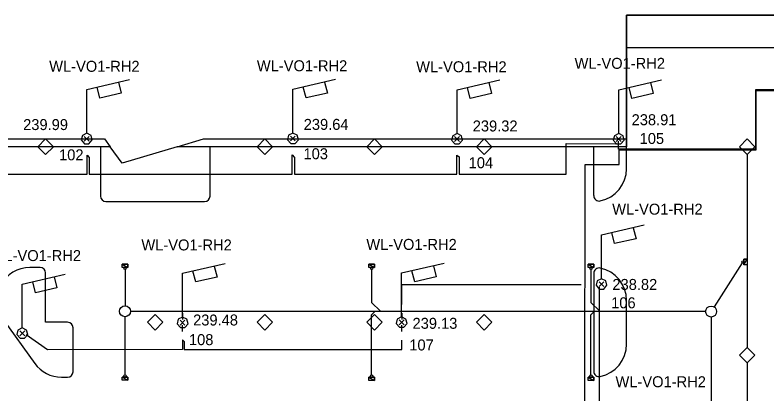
# Model space of a CAD drawing. Extents: x -264222 to -263592, y -1242345 to -1242048.
# Drawn here: x -264187.4 to -264118.8, y -1242214 to -1242179.5 of the extents above; entities that cross this region are included whole.
import ezdxf

# ---------------------------------------------------------------- set-up
doc = ezdxf.new("R2010")
doc.units = 0
for name, color, linetype in [('BOD_CISLO', 7, 'Continuous'), ('BOD_SYMBOL', 7, 'Continuous'), ('BOD_VYSKA', 7, 'Continuous'), ('KFA_2D_SITUACIA_DSP', 7, 'Continuous'), ('KFA_SO_62-1_VO_LAMPY_MERANE', 7, 'Continuous'), ('KFA_SO_62-1_VO_POPIS_LAMP_PROJEKT', 7, 'Continuous'), ('KFA_SO_62-1_VO_TRASA_KABLOV_PROJEKT', 7, 'Continuous')]:
    doc.layers.add(name, color=color, linetype=linetype)

msp = doc.modelspace()

# ---------------------------------------------------------------- linework, layer by layer
at = {"layer": 'BOD_SYMBOL'}
for p, q in [((-264181.038, -1242190.978), (-264180.596, -1242190.536)), ((-264180.596, -1242190.978), (-264181.038, -1242190.536)), ((-264162.233, -1242190.96), (-264161.791, -1242190.518)), ((-264161.791, -1242190.96), (-264162.233, -1242190.518)), ((-264147.253, -1242191.004), (-264146.811, -1242190.562)), ((-264146.811, -1242191.004), (-264147.253, -1242190.562)), ((-264132.505, -1242191.004), (-264132.063, -1242190.562)), ((-264132.063, -1242191.004), (-264132.505, -1242190.562)), ((-264134.077, -1242204.234), (-264133.635, -1242203.792)), ((-264133.635, -1242204.234), (-264134.077, -1242203.792)), ((-264172.299, -1242207.73), (-264171.857, -1242207.288)), ((-264171.857, -1242207.73), (-264172.299, -1242207.288)), ((-264152.316, -1242207.709), (-264151.874, -1242207.267)), ((-264151.874, -1242207.709), (-264152.316, -1242207.267)), ((-264186.919, -1242208.714), (-264186.477, -1242208.272)), ((-264186.477, -1242208.714), (-264186.919, -1242208.272))]:
    msp.add_line(p, q, dxfattribs=at)
at = {"layer": 'KFA_2D_SITUACIA_DSP'}
for p, q in [((-264131.568, -1242193.482), (-264131.568, -1242179.482)), ((-264077.23, -1242179.482), (-264131.568, -1242179.482)), ((-264131.568, -1242179.482), (-264131.568, -1242191.482)), ((-264131.568, -1242179.482), (-263959.468, -1242179.482)), ((-263959.468, -1242179.482), (-264131.568, -1242179.482)), ((-264045.204, -1242182.482), (-264131.568, -1242182.482)), ((-264205.202, -1242190.775), (-264179.193, -1242190.775)), ((-264179.193, -1242190.775), (-264178.679, -1242191.482)), ((-264172.558, -1242191.482), (-264170.162, -1242190.775)), ((-264170.162, -1242190.775), (-264131.568, -1242190.775)), ((-264178.679, -1242191.482), (-264204.694, -1242191.482)), ((-264179.568, -1242191.482), (-264204.078, -1242191.482)), ((-264179.568, -1242191.482), (-264179.568, -1242195.982)), ((-264177.6, -1242192.97), (-264178.679, -1242191.482)), ((-264172.558, -1242191.482), (-264177.6, -1242192.97)), ((-264131.568, -1242191.482), (-264172.558, -1242191.482)), ((-264134.568, -1242191.482), (-264169.568, -1242191.482)), ((-264169.568, -1242195.982), (-264169.568, -1242191.482)), ((-264134.568, -1242195.932), (-264134.568, -1242191.482)), ((-264120.568, -1242192.189), (-264120.568, -1242209.775)), ((-264179.068, -1242196.482), (-264170.068, -1242196.482)), ((-264121.012, -1242202.066), (-264123.585, -1242206.079)), ((-264120.858, -1242202.232), (-264120.858, -1242201.732)), ((-264120.858, -1242201.732), (-264120.568, -1242201.732)), ((-264120.858, -1242202.232), (-264120.568, -1242201.732)), ((-264120.858, -1242202.232), (-264120.568, -1242201.732)), ((-264120.568, -1242201.732), (-264120.858, -1242201.732)), ((-264120.858, -1242201.732), (-264120.858, -1242202.232)), ((-264120.568, -1242201.732), (-264120.568, -1242202.232)), ((-264185.068, -1242202.482), (-264186.002, -1242202.482)), ((-264177.574, -1242202.186), (-264177.074, -1242202.186)), ((-264177.574, -1242202.476), (-264177.574, -1242202.186)), ((-264177.574, -1242202.186), (-264177.074, -1242202.476)), ((-264177.574, -1242202.186), (-264177.074, -1242202.476)), ((-264177.074, -1242202.186), (-264177.574, -1242202.186)), ((-264177.074, -1242202.476), (-264177.574, -1242202.476)), ((-264177.324, -1242202.676), (-264177.324, -1242205.976)), ((-264177.074, -1242202.186), (-264177.074, -1242202.476)), ((-264177.074, -1242202.476), (-264177.074, -1242202.186)), ((-264155.074, -1242202.192), (-264154.574, -1242202.192)), ((-264155.074, -1242202.482), (-264155.074, -1242202.192)), ((-264155.074, -1242202.192), (-264154.574, -1242202.482)), ((-264155.074, -1242202.192), (-264154.574, -1242202.482)), ((-264154.574, -1242202.192), (-264155.074, -1242202.192)), ((-264154.574, -1242202.482), (-264155.074, -1242202.482)), ((-264154.824, -1242202.682), (-264154.824, -1242205.68)), ((-264154.574, -1242202.192), (-264154.574, -1242202.482)), ((-264154.574, -1242202.482), (-264154.574, -1242202.192)), ((-264135.068, -1242202.192), (-264134.568, -1242202.192)), ((-264135.068, -1242202.482), (-264135.068, -1242202.192)), ((-264135.068, -1242202.192), (-264134.568, -1242202.482)), ((-264135.068, -1242202.192), (-264134.568, -1242202.482)), ((-264134.568, -1242202.192), (-264135.068, -1242202.192)), ((-264134.568, -1242202.482), (-264135.068, -1242202.482)), ((-264134.818, -1242202.682), (-264134.818, -1242205.68)), ((-264134.568, -1242202.192), (-264134.568, -1242202.482)), ((-264134.568, -1242202.482), (-264134.568, -1242202.192)), ((-264120.568, -1242202.232), (-264120.858, -1242202.232)), ((-264134.568, -1242203.033), (-264134.568, -1242211.932)), ((-264131.568, -1242209.482), (-264131.568, -1242205.482)), ((-264154.824, -1242205.68), (-264154.029, -1242206.476)), ((-264134.818, -1242205.68), (-264134.023, -1242206.476)), ((-264176.824, -1242206.476), (-264124.354, -1242206.476)), ((-264154.824, -1242206.801), (-264154.499, -1242206.476)), ((-264154.824, -1242212.282), (-264154.824, -1242206.801)), ((-264134.818, -1242206.801), (-264134.493, -1242206.476)), ((-264134.818, -1242212.282), (-264134.818, -1242206.801)), ((-264188.438, -1242207.234), (-264185.561, -1242211.234)), ((-264177.324, -1242212.276), (-264177.324, -1242206.976)), ((-264123.854, -1242207), (-264123.854, -1242236.976)), ((-264182.068, -1242211.982), (-264182.068, -1242207.982)), ((-264120.568, -1242211.189), (-264120.568, -1242219.774)), ((-264183.125, -1242212.482), (-264182.568, -1242212.482)), ((-264177.574, -1242212.476), (-264177.074, -1242212.476)), ((-264177.574, -1242212.766), (-264177.574, -1242212.476)), ((-264177.574, -1242212.476), (-264177.074, -1242212.766)), ((-264177.574, -1242212.476), (-264177.074, -1242212.766)), ((-264177.074, -1242212.476), (-264177.574, -1242212.476)), ((-264177.074, -1242212.766), (-264177.574, -1242212.766)), ((-264177.074, -1242212.476), (-264177.074, -1242212.766)), ((-264177.074, -1242212.766), (-264177.074, -1242212.476)), ((-264155.074, -1242212.482), (-264154.574, -1242212.482)), ((-264155.074, -1242212.772), (-264155.074, -1242212.482)), ((-264155.074, -1242212.482), (-264154.574, -1242212.772)), ((-264155.074, -1242212.482), (-264154.574, -1242212.772)), ((-264154.574, -1242212.482), (-264155.074, -1242212.482)), ((-264154.574, -1242212.772), (-264155.074, -1242212.772)), ((-264154.574, -1242212.482), (-264154.574, -1242212.772)), ((-264154.574, -1242212.772), (-264154.574, -1242212.482)), ((-264135.068, -1242212.482), (-264134.568, -1242212.482)), ((-264135.068, -1242212.772), (-264135.068, -1242212.482)), ((-264135.068, -1242212.482), (-264134.568, -1242212.772)), ((-264135.068, -1242212.482), (-264134.568, -1242212.772)), ((-264134.568, -1242212.482), (-264135.068, -1242212.482)), ((-264134.568, -1242212.772), (-264135.068, -1242212.772)), ((-264134.568, -1242212.482), (-264134.568, -1242212.772)), ((-264134.568, -1242212.772), (-264134.568, -1242212.482))]:
    msp.add_line(p, q, dxfattribs=at)
for points in [[(-264184.568, -1242190.775), (-264183.861, -1242191.482), (-264184.568, -1242192.189), (-264185.275, -1242191.482)], [(-264164.568, -1242190.775), (-264163.861, -1242191.482), (-264164.568, -1242192.189), (-264165.275, -1242191.482)], [(-264154.568, -1242190.775), (-264153.861, -1242191.482), (-264154.568, -1242192.189), (-264155.275, -1242191.482)], [(-264144.568, -1242190.775), (-264143.861, -1242191.482), (-264144.568, -1242192.189), (-264145.275, -1242191.482)], [(-264120.568, -1242190.775), (-264119.861, -1242191.482), (-264120.568, -1242192.189), (-264121.275, -1242191.482)], [(-264173.861, -1242207.482), (-264174.568, -1242206.775), (-264175.275, -1242207.482), (-264174.568, -1242208.189)], [(-264163.861, -1242207.482), (-264164.568, -1242206.775), (-264165.275, -1242207.482), (-264164.568, -1242208.189)], [(-264153.861, -1242207.482), (-264154.568, -1242206.775), (-264155.275, -1242207.482), (-264154.568, -1242208.189)], [(-264143.861, -1242207.482), (-264144.568, -1242206.775), (-264145.275, -1242207.482), (-264144.568, -1242208.189)], [(-264120.568, -1242209.775), (-264119.861, -1242210.482), (-264120.568, -1242211.189), (-264121.275, -1242210.482)]]:
    msp.add_lwpolyline(points, close=True, dxfattribs=at)
for points in [[(-264183.861, -1242191.482), (-264183.861, -1242191.482), (-264184.568, -1242192.189), (-264185.275, -1242191.482)], [(-264163.861, -1242191.482), (-264163.861, -1242191.482), (-264164.568, -1242192.189), (-264165.275, -1242191.482)], [(-264153.861, -1242191.482), (-264153.861, -1242191.482), (-264154.568, -1242192.189), (-264155.275, -1242191.482)], [(-264143.861, -1242191.482), (-264143.861, -1242191.482), (-264144.568, -1242192.189), (-264145.275, -1242191.482)], [(-264182.568, -1242207.482), (-264184.568, -1242207.482), (-264184.568, -1242202.982)]]:
    msp.add_lwpolyline(points, dxfattribs=at)
for centre, radius in [((-264120.958, -1242201.982), 0.1), ((-264177.324, -1242202.576), 0.1), ((-264154.824, -1242202.582), 0.1), ((-264134.818, -1242202.582), 0.1), ((-264177.324, -1242206.476), 0.5), ((-264123.854, -1242206.5), 0.5), ((-264177.324, -1242212.376), 0.1), ((-264154.824, -1242212.382), 0.1), ((-264134.818, -1242212.382), 0.1)]:
    msp.add_circle(centre, radius, dxfattribs=at)
for centre, radius, start, end in [((-264134.568, -1242193.482), 3, 281.53696, 0), ((-264179.068, -1242195.982), 0.5, 180, 270), ((-264170.068, -1242195.982), 0.5, 270, 0), ((-264134.068, -1242195.932), 0.5, 180, 281.53696), ((-264186.002, -1242205.482), 3, 90, 215.72401), ((-264185.068, -1242202.982), 0.5, 0, 90), ((-264134.068, -1242203.033), 0.5, 78.46304, 180), ((-264134.568, -1242205.482), 3, 0, 78.46304), ((-264182.568, -1242207.982), 0.5, 0, 90), ((-264134.568, -1242209.482), 3, 281.53696, 0), ((-264183.125, -1242209.482), 3, 215.72401, 270), ((-264182.568, -1242211.982), 0.5, 270, 0), ((-264134.068, -1242211.932), 0.5, 180, 281.53696)]:
    msp.add_arc(centre, radius, start, end, dxfattribs=at)
at = {"layer": 'KFA_SO_62-1_VO_LAMPY_MERANE'}
for p, q in [((-264180.867, -1242190.757), (-264180.767, -1242190.757)), ((-264180.817, -1242190.757), (-264180.817, -1242190.757)), ((-264162.062, -1242190.739), (-264161.962, -1242190.739)), ((-264162.012, -1242190.739), (-264162.012, -1242190.739)), ((-264147.082, -1242190.783), (-264146.982, -1242190.783)), ((-264147.032, -1242190.783), (-264147.032, -1242190.783)), ((-264132.334, -1242190.783), (-264132.234, -1242190.783)), ((-264132.284, -1242190.783), (-264132.284, -1242190.783)), ((-264133.906, -1242204.013), (-264133.806, -1242204.013)), ((-264133.856, -1242204.013), (-264133.856, -1242204.013)), ((-264172.128, -1242207.509), (-264172.028, -1242207.509)), ((-264172.078, -1242207.509), (-264172.078, -1242207.509)), ((-264152.145, -1242207.488), (-264152.045, -1242207.488)), ((-264152.095, -1242207.488), (-264152.095, -1242207.488)), ((-264186.748, -1242208.493), (-264186.648, -1242208.493)), ((-264186.698, -1242208.493), (-264186.698, -1242208.493))]:
    msp.add_line(p, q, dxfattribs=at)
for points in [[(-264180.817, -1242190.257), (-264181.217, -1242190.457), (-264181.317, -1242190.857), (-264181.017, -1242191.207), (-264180.617, -1242191.207), (-264180.317, -1242190.857), (-264180.417, -1242190.457), (-264180.817, -1242190.257), (-264180.817, -1242186.257), (-264176.917, -1242185.357)], [(-264177.917, -1242185.607), (-264177.667, -1242186.607), (-264179.617, -1242187.057), (-264179.867, -1242186.057)], [(-264162.012, -1242190.239), (-264162.412, -1242190.439), (-264162.512, -1242190.839), (-264162.212, -1242191.189), (-264161.812, -1242191.189), (-264161.512, -1242190.839), (-264161.612, -1242190.439), (-264162.012, -1242190.239), (-264162.012, -1242186.239), (-264158.112, -1242185.339)], [(-264159.112, -1242185.589), (-264158.862, -1242186.589), (-264160.812, -1242187.039), (-264161.062, -1242186.039)], [(-264147.032, -1242190.283), (-264147.432, -1242190.483), (-264147.532, -1242190.883), (-264147.232, -1242191.233), (-264146.832, -1242191.233), (-264146.532, -1242190.883), (-264146.632, -1242190.483), (-264147.032, -1242190.283), (-264147.032, -1242186.283), (-264143.132, -1242185.383)], [(-264132.284, -1242190.283), (-264132.684, -1242190.483), (-264132.784, -1242190.883), (-264132.484, -1242191.233), (-264132.084, -1242191.233), (-264131.784, -1242190.883), (-264131.884, -1242190.483), (-264132.284, -1242190.283), (-264132.284, -1242186.283), (-264128.384, -1242185.383)], [(-264144.132, -1242185.633), (-264143.882, -1242186.633), (-264145.832, -1242187.083), (-264146.082, -1242186.083)], [(-264129.384, -1242185.633), (-264129.134, -1242186.633), (-264131.084, -1242187.083), (-264131.334, -1242186.083)], [(-264133.856, -1242203.513), (-264134.256, -1242203.713), (-264134.356, -1242204.113), (-264134.056, -1242204.463), (-264133.656, -1242204.463), (-264133.356, -1242204.113), (-264133.456, -1242203.713), (-264133.856, -1242203.513), (-264133.856, -1242199.513), (-264129.956, -1242198.613)], [(-264130.956, -1242198.863), (-264130.706, -1242199.863), (-264132.656, -1242200.313), (-264132.906, -1242199.313)], [(-264172.078, -1242207.009), (-264172.478, -1242207.209), (-264172.578, -1242207.609), (-264172.278, -1242207.959), (-264171.878, -1242207.959), (-264171.578, -1242207.609), (-264171.678, -1242207.209), (-264172.078, -1242207.009), (-264172.078, -1242203.009), (-264168.178, -1242202.109)], [(-264169.178, -1242202.359), (-264168.928, -1242203.359), (-264170.878, -1242203.809), (-264171.128, -1242202.809)], [(-264152.095, -1242206.988), (-264152.495, -1242207.188), (-264152.595, -1242207.588), (-264152.295, -1242207.938), (-264151.895, -1242207.938), (-264151.595, -1242207.588), (-264151.695, -1242207.188), (-264152.095, -1242206.988), (-264152.095, -1242202.988), (-264148.195, -1242202.088)], [(-264149.195, -1242202.338), (-264148.945, -1242203.338), (-264150.895, -1242203.788), (-264151.145, -1242202.788)], [(-264186.698, -1242207.993), (-264187.098, -1242208.193), (-264187.198, -1242208.593), (-264186.898, -1242208.943), (-264186.498, -1242208.943), (-264186.198, -1242208.593), (-264186.298, -1242208.193), (-264186.698, -1242207.993), (-264186.698, -1242203.993), (-264182.798, -1242203.093)], [(-264183.798, -1242203.343), (-264183.548, -1242204.343), (-264185.498, -1242204.793), (-264185.748, -1242203.793)]]:
    msp.add_lwpolyline(points, dxfattribs=at)
at = {"layer": 'KFA_SO_62-1_VO_TRASA_KABLOV_PROJEKT'}
for p, q in [((-263948.695, -1242186.3), (-264119.795, -1242186.3)), ((-264119.795, -1242186.3), (-264119.795, -1242191.7)), ((-264119.745, -1242191.75), (-264119.745, -1242186.35)), ((-264119.745, -1242186.35), (-264110.745, -1242186.35)), ((-264132.295, -1242191.7), (-264132.3, -1242190.965)), ((-264137.068, -1242193.982), (-264137.068, -1242191.2)), ((-264137.068, -1242191.2), (-264132.55, -1242191.215)), ((-264119.795, -1242191.7), (-264132.295, -1242191.7)), ((-264132.245, -1242193.1), (-264132.245, -1242191.75)), ((-264132.245, -1242191.75), (-264119.745, -1242191.75)), ((-264180.79, -1242193.982), (-264180.79, -1242192.263)), ((-264180.79, -1242192.263), (-264180.59, -1242192.463)), ((-264180.59, -1242192.463), (-264180.59, -1242193.982)), ((-264162.068, -1242193.982), (-264162.068, -1242192.232)), ((-264162.068, -1242192.232), (-264161.865, -1242192.449)), ((-264161.865, -1242192.449), (-264161.865, -1242193.982)), ((-264147.068, -1242193.982), (-264147.068, -1242192.24)), ((-264147.068, -1242192.24), (-264146.847, -1242192.396)), ((-264146.847, -1242192.396), (-264146.847, -1242193.982)), ((-264135.375, -1242250.669), (-264135.36, -1242193.1)), ((-264135.36, -1242193.1), (-264132.245, -1242193.1)), ((-264198.313, -1242193.982), (-264180.79, -1242193.982)), ((-264180.59, -1242193.982), (-264162.068, -1242193.982)), ((-264161.865, -1242193.982), (-264147.068, -1242193.982)), ((-264146.847, -1242193.982), (-264137.068, -1242193.982)), ((-264152.069, -1242205.863), (-264152.069, -1242204.05)), ((-264152.069, -1242204.05), (-264135.697, -1242204.05)), ((-264134.075, -1242204.292), (-264134.075, -1242219.722)), ((-264172.069, -1242206.649), (-264172.069, -1242207.232)), ((-264152.066, -1242206.649), (-264152.066, -1242207.232)), ((-264172.069, -1242208.316), (-264172.069, -1242207.732)), ((-264152.066, -1242208.316), (-264152.066, -1242207.732)), ((-264184.393, -1242209.982), (-264186.349, -1242208.623)), ((-264172.069, -1242209.085), (-264172.069, -1242209.97)), ((-264172.069, -1242209.085), (-264171.941, -1242209.229)), ((-264171.941, -1242209.229), (-264171.941, -1242209.97)), ((-264152.068, -1242209.97), (-264152.068, -1242209.108)), ((-264172.069, -1242209.97), (-264184.393, -1242209.982)), ((-264171.941, -1242209.97), (-264152.068, -1242209.97))]:
    msp.add_line(p, q, dxfattribs=at)

# ---------------------------------------------------------------- texts
at = {"layer": 'BOD_CISLO'}
for s, p in [('105', (-264130.376, -1242191.231)), ('102', (-264183.341, -1242192.722)), ('103', (-264161.043, -1242192.623)), ('104', (-264145.975, -1242193.438)), ('106', (-264132.976, -1242206.206)), ('108', (-264171.491, -1242209.564)), ('107', (-264151.391, -1242210.05))]:
    msp.add_text(s, height=1, dxfattribs=at).set_placement(p)
at = {"layer": 'BOD_VYSKA'}
for s, p in [('239.99', (-264186.619, -1242189.964)), ('239.64', (-264161.023, -1242189.946)), ('238.91', (-264131.108, -1242189.52)), ('239.32', (-264145.603, -1242190.09)), ('238.82', (-264132.862, -1242204.532)), ('239.48', (-264171.113, -1242207.773)), ('239.13', (-264151.095, -1242208.075))]:
    msp.add_text(s, height=1, dxfattribs=at).set_placement(p)
at = {"layer": 'KFA_SO_62-1_VO_POPIS_LAMP_PROJEKT'}
for p in [(-264136.312, -1242184.383), (-264184.244, -1242184.654), (-264165.298, -1242184.604), (-264150.762, -1242184.696), (-264132.88, -1242197.673), (-264175.831, -1242200.933), (-264155.308, -1242200.884), (-264189.584, -1242201.901), (-264132.579, -1242213.4)]:
    msp.add_text('WL-VO1-RH2', height=1, dxfattribs=at).set_placement(p)

doc.saveas('drawing.dxf')
